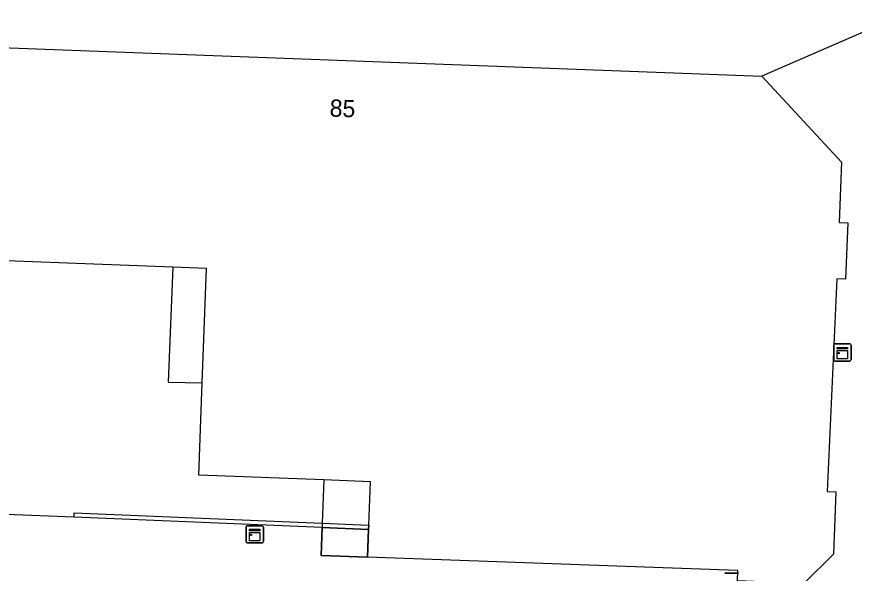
# Model space of a CAD drawing. Extents: x 160891 to 161384, y 386490 to 386907.
# Drawn here: x 161047.88 to 161096.46, y 386839.4 to 386871.67 of the extents above; entities that cross this region are included whole.
import ezdxf

# ---------------------------------------------------------------- set-up
doc = ezdxf.new("R2010")
doc.units = 0
for name, color, linetype in [('IMGEO_Afvalbak', 7, 'Continuous'), ('IMGEO_Kast', 7, 'Continuous'), ('IMGEO_Muur', 7, 'Continuous'), ('IMGEO_Pand', 7, 'Continuous'), ('IMGEO_Pand_nummerreeks', 7, 'Continuous'), ('IMGEO_Pand_overbouw', 7, 'Continuous'), ('IMGEO_Voetgangersgebied_open', 7, 'Continuous'), ('IMGEO_Voetpad_open', 7, 'Continuous')]:
    doc.layers.add(name, color=color, linetype=linetype)

msp = doc.modelspace()

# ---------------------------------------------------------------- linework, layer by layer
at = {"layer": 'IMGEO_Afvalbak'}
for p, q in [((161088.96, 386839.396), (161089.75, 386839.396)), ((161089.75, 386839.396), (161088.96, 386839.396))]:
    msp.add_line(p, q, dxfattribs=at)
at = {"layer": 'IMGEO_Kast'}
for p, q in [((161095.354, 386852.702), (161096.195, 386852.702)), ((161096.195, 386852.702), (161095.354, 386852.702)), ((161095.279, 386851.777), (161095.279, 386852.618)), ((161095.279, 386852.618), (161095.279, 386851.777)), ((161096.279, 386852.627), (161096.279, 386851.786)), ((161096.279, 386851.786), (161096.279, 386852.627)), ((161096.204, 386851.702), (161095.363, 386851.702)), ((161095.363, 386851.702), (161096.204, 386851.702)), ((161061.189, 386841.227), (161061.189, 386842.068)), ((161061.189, 386842.068), (161061.189, 386841.227)), ((161061.264, 386842.152), (161062.105, 386842.152)), ((161062.105, 386842.152), (161061.264, 386842.152)), ((161062.189, 386842.077), (161062.189, 386841.236)), ((161062.189, 386841.236), (161062.189, 386842.077)), ((161062.114, 386841.152), (161061.273, 386841.152)), ((161061.273, 386841.152), (161062.114, 386841.152))]:
    msp.add_line(p, q, dxfattribs=at)
for points in [[(161095.474, 386852.492), (161096.074, 386852.492), (161096.074, 386852.407), (161095.474, 386852.407), (161095.474, 386852.492)], [(161095.474, 386852.317), (161096.074, 386852.317), (161096.074, 386851.828), (161095.474, 386851.828), (161095.474, 386852.317)], [(161061.384, 386841.942), (161061.984, 386841.942), (161061.984, 386841.857), (161061.384, 386841.857), (161061.384, 386841.942)], [(161061.384, 386841.767), (161061.984, 386841.767), (161061.984, 386841.278), (161061.384, 386841.278), (161061.384, 386841.767)]]:
    msp.add_lwpolyline(points, dxfattribs=at)
for centre in [(161095.558, 386852.166), (161061.468, 386841.616)]:
    msp.add_circle(centre, 0.0377, dxfattribs=at)
for centre, start, end in [((161095.357, 386852.624), 92.4484, 184.2845), ((161095.357, 386852.624), 92.4484, 184.2845), ((161096.201, 386852.624), 2.4484, 94.2845), ((161096.201, 386852.624), 2.4484, 94.2845), ((161095.357, 386851.78), 182.4484, 274.2845), ((161095.357, 386851.78), 182.4484, 274.2845), ((161096.201, 386851.78), 272.4484, 4.2845), ((161096.201, 386851.78), 272.4484, 4.2845), ((161061.267, 386842.074), 92.4484, 184.2845), ((161061.267, 386842.074), 92.4484, 184.2845), ((161062.111, 386842.074), 2.4484, 94.2845), ((161062.111, 386842.074), 2.4484, 94.2845), ((161061.267, 386841.23), 182.4484, 274.2845), ((161061.267, 386841.23), 182.4484, 274.2845), ((161062.111, 386841.23), 272.4484, 4.2845), ((161062.111, 386841.23), 272.4484, 4.2845)]:
    msp.add_arc(centre, 0.0779, start, end, dxfattribs=at)
at = {"layer": 'IMGEO_Muur'}
for points in [[(161051.209, 386842.641), (161051.22, 386842.901), (161065.605, 386842.299)], [(161065.595, 386842.039), (161051.209, 386842.641)], [(161065.605, 386842.299), (161065.595, 386842.039)], [(161068.295, 386841.926), (161065.595, 386842.039)], [(161065.605, 386842.299), (161068.305, 386842.186)]]:
    msp.add_lwpolyline(points, dxfattribs=at)
at = {"layer": 'IMGEO_Pand'}
for points in [[(161042.835, 386870.038), (161086.005, 386868.407), (161091.101, 386868.215)], [(161091.101, 386868.215), (161095.717, 386863.238), (161095.585, 386859.74), (161096.085, 386859.722), (161095.962, 386856.455), (161095.463, 386856.474), (161094.893, 386844.136), (161095.392, 386844.117), (161095.255, 386840.499), (161093.53, 386838.801), (161089.69, 386838.959), (161089.715, 386839.558), (161084.829, 386839.735), (161068.235, 386840.335)], [(161068.305, 386842.186), (161068.399, 386844.702), (161065.695, 386844.804), (161058.44, 386845.077), (161058.642, 386850.434), (161058.893, 386857.072), (161056.937, 386857.146), (161042.665, 386857.686)], [(161068.305, 386842.186), (161068.295, 386841.926)], [(161068.295, 386841.926), (161068.235, 386840.335)]]:
    msp.add_lwpolyline(points, dxfattribs=at)
at = {"layer": 'IMGEO_Pand_overbouw'}
for points in [[(161056.937, 386857.146), (161056.656, 386850.47), (161058.642, 386850.434), (161058.893, 386857.072)], [(161065.695, 386844.804), (161065.605, 386842.299), (161065.596, 386842.062), (161065.595, 386842.039), (161065.537, 386840.433), (161068.235, 386840.335), (161068.295, 386841.926), (161068.305, 386842.186), (161068.399, 386844.702)]]:
    msp.add_lwpolyline(points, close=True, dxfattribs=at)
at = {"layer": 'IMGEO_Voetgangersgebied_open'}
for points in [[(161051.209, 386842.641), (161047.24, 386842.811)], [(161068.235, 386840.335), (161065.537, 386840.433), (161065.595, 386842.039)]]:
    msp.add_lwpolyline(points, dxfattribs=at)
at = {"layer": 'IMGEO_Voetpad_open'}
for points in [[(161100.979, 386872.509), (161091.101, 386868.215)], [(161065.595, 386842.039), (161068.295, 386841.926)], [(161065.605, 386842.299), (161068.305, 386842.186)]]:
    msp.add_lwpolyline(points, dxfattribs=at)

# ---------------------------------------------------------------- texts
at = {"layer": 'IMGEO_Pand_nummerreeks'}
msp.add_text('85', height=1, rotation=357.837, dxfattribs=at).set_placement((161066.019, 386865.881))

doc.saveas('drawing.dxf')
